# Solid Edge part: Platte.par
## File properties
Author: bmolnar
Template: iso metric part.par
Last saved by: bmolnar
Revision: 2
Application: Solid Edge
Sűrűség: 0,000 kg/m^3
Pontosság: 0,990
Username: bmolnar
Dokumentum tartalom típus: 0
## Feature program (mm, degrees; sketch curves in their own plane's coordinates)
base feature "unnamed BaseFeature 1"
sketch for "unnamed Protrusion 1" plane through (-13.75, -0.5, 30.7901) normal (0, 1, 0) x-axis (1, 0, 0)
  circle centre (0, 0.6988) radius 12.5
extrude "unnamed Protrusion 1" add finite 26 along +normal
sketch for "Kihúzás_2" plane through (-13.75, -144.5, 30.7901) normal (0, -1, 0) x-axis (-1, 0, 0)
  circle centre (0, 0.6988) radius 12.5
extrude "Kihúzás_2" add finite 26 along +normal
sketch for "Furat_1" plane through (-0.75, -72.5, -3.9087) normal (0, 0, -1) x-axis (0, 1, 0)
  line (0, 0) -> (0, 0)
  hole centre (-45, 0.5) bore radius 2.4585
hole "Furat_1" nominal diameter 6  ThreadDepth = 8 mm
sketch for "unnamed Hole 1" plane through (-0.75, -72.5, -3.9087) normal (0, 0, -1) x-axis (0, 1, 0)
  hole centre (0, 0.5) bore radius 2.4585
hole "unnamed Hole 1"
sketch for "unnamed Hole 2" plane through (-0.75, -72.5, -3.9087) normal (0, 0, -1) x-axis (0, 1, 0)
  hole centre (45, 0.5) bore radius 2.4585
hole "unnamed Hole 2"
sketch for "unnamed Hole 3" plane through (-0.75, -72.5, -3.9087) normal (0, 0, -1) x-axis (0, 1, 0)
  hole centre (45, -26.5) bore radius 2.4585
hole "unnamed Hole 3"
sketch for "unnamed Hole 4" plane through (-0.75, -72.5, -3.9087) normal (0, 0, -1) x-axis (0, 1, 0)
  hole centre (0, -26.5) bore radius 2.4585
hole "unnamed Hole 4"
sketch for "unnamed Hole 5" plane through (-0.75, -72.5, -3.9087) normal (0, 0, -1) x-axis (0, 1, 0)
  hole centre (-45, -26.5) bore radius 2.4585
hole "unnamed Hole 5"
pattern "unnamed Pattern 1" of "Furat_1", "unnamed Hole 1", "unnamed Hole 2", "unnamed Hole 3", "unnamed Hole 4", "unnamed Hole 5"
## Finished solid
Body 1: solid body, 153 faces, 330 edges, 186 vertices, 8 internal voids.
  Faces by surface: plane 100, cylinder 45, cone 4, torus 4
  Edges by curve: line 238, circle 92
Bounding box of the edges (mm; curved faces can reach further): 36.000 x 196.000 x 47.900, from (-31.75, -170.5, -3.9087) to (4.25, 25.5, 43.9913).
Cylindrical faces by radius (mm): R1 x2, R1.2295 x4, R1.5 x4, R1.6 x8, R2.4585 x12, R2.75 x4, R2.9996 x6, R3 x2, R12.5 x2, R13.9 x1
Conical faces (half-angle, radius in mm at the cone's reference point): 59 deg R1.2295 x4
Toroidal faces (ring radius, tube radius in mm): R1.6 r0.1 x4
Planar faces by outward normal: +x 12, +y 15, +z 3, -x 12, -y 15, -z 11, oblique 32
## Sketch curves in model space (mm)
circle centre (-13.75, -144.5, 30.0913) radius 12.5
circle centre (-13.75, -0.5, 30.0913) radius 12.5
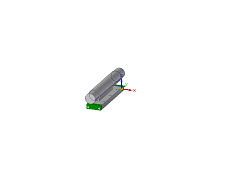
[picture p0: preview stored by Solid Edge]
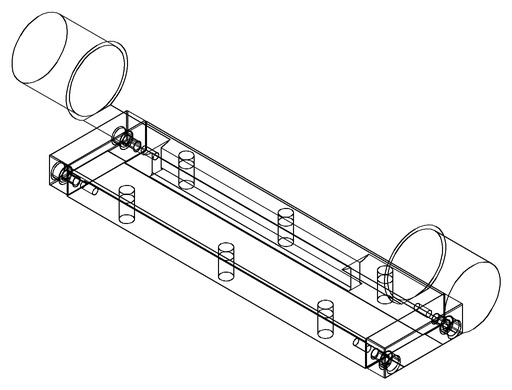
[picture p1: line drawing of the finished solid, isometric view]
